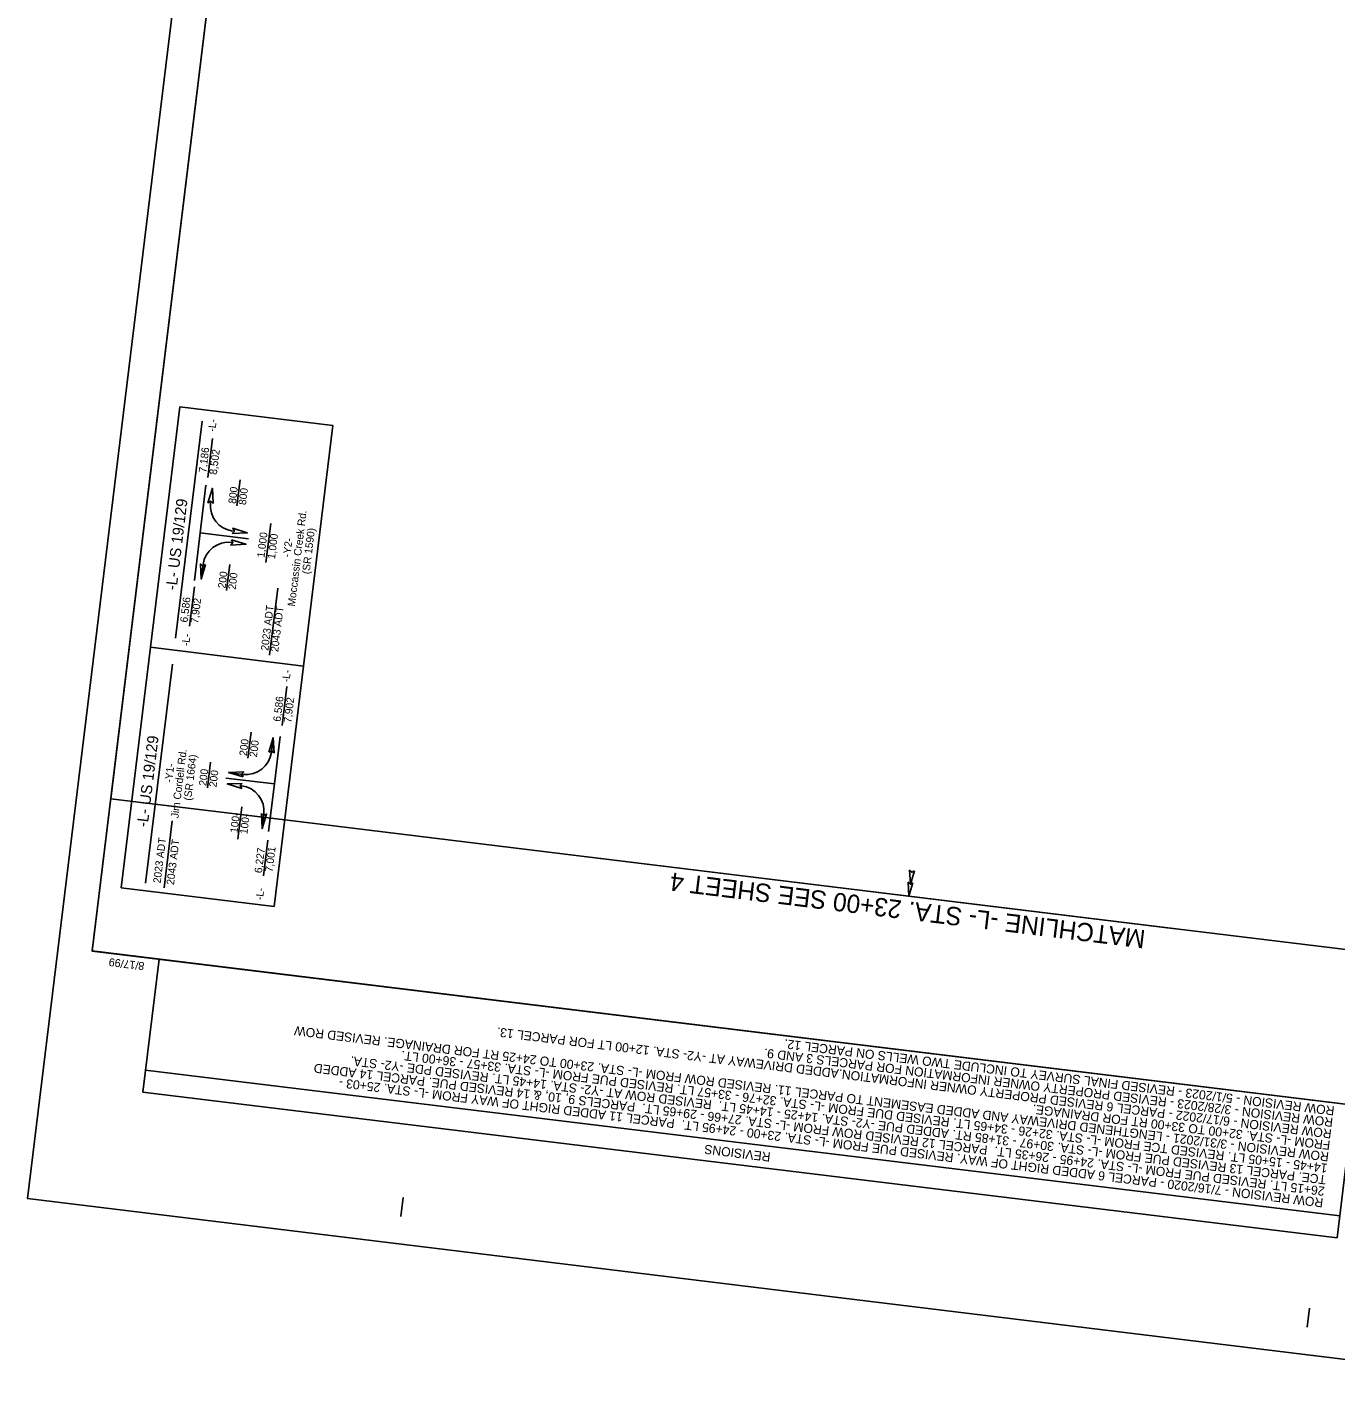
# Model space of a CAD drawing. Extents: x 480792 to 482083, y 490046 to 491850.
# Drawn here: x 480792 to 481651, y 490046 to 490948 of the extents above; entities that cross this region are included whole.
import ezdxf

# ---------------------------------------------------------------- set-up
doc = ezdxf.new("R2010")
doc.units = 0
for name, color, linetype in [('Matchline', 7, 'Continuous'), ('Matchline Text', 7, 'Continuous'), ('Prop DSN Text', 7, 'Continuous'), ('Prop Grid Mask', 7, 'Continuous'), ('Prop PHM Traffic Signal CELL', 7, 'Continuous'), ('Prop Terminator CELL', 7, 'Continuous'), ('Sheet Block Revision CELL', 7, 'Continuous'), ('Sheet Clip Boundary CELL', 7, 'Continuous'), ('Sheet Plan CELL', 7, 'Continuous'), ('Sheet Plot Border Outside CELL', 7, 'Continuous')]:
    doc.layers.add(name, color=color, linetype=linetype)

msp = doc.modelspace()

# ---------------------------------------------------------------- linework, layer by layer
at = {"layer": 'Matchline'}
msp.add_line((481546.32, 490356.15), (481123.7, 490407.77), dxfattribs=at)
at = {"layer": 'Prop DSN Text'}
for p, q in [((480937.18, 490612.39), (480905.3, 490616.28)), ((480922.18, 490455.2), (480954.06, 490451.31)), ((480923.98, 490458.77), (480933.43, 490457.61))]:
    msp.add_line(p, q, dxfattribs=at)
for points in [[(480913.77, 490635.61), (480913.36, 490645.56), (480910.4, 490636.02), (480912.33, 490637.05)], [(480926.35, 490615.87), (480936.3, 490616.28), (480926.76, 490619.24), (480927.79, 490617.31)], [(480925.83, 490611.61), (480935.39, 490608.82), (480925.42, 490608.24), (480926.88, 490609.87)], [(480908.87, 490595.48), (480906.08, 490585.92), (480905.5, 490595.89), (480907.12, 490594.43)], [(480950.5, 490472.11), (480953.29, 490481.66), (480953.86, 490471.69), (480952.24, 490473.15)], [(480933.53, 490455.97), (480923.98, 490458.77), (480933.95, 490459.34), (480932.49, 490457.72)], [(480933.01, 490451.72), (480923.07, 490451.31), (480932.6, 490448.35), (480931.58, 490450.27)], [(480945.59, 490431.97), (480946.01, 490422.03), (480948.96, 490431.57), (480947.04, 490430.54)]]:
    msp.add_lwpolyline(points, close=True, dxfattribs=at)
for centre, start, end in [((480928.86, 490634.08), 173.08207, 263.08206), ((480923.89, 490593.33), 82.99191, 172.99189), ((480935.48, 490474.25), 262.99191, 352.99189), ((480930.5, 490433.51), 353.08207, 83.08206)]:
    msp.add_arc(centre, 16.77, start, end, dxfattribs=at)
at = {"layer": 'Prop Grid Mask'}
for points in [[(480872.76, 490541.08), (480892.05, 490698.98), (480992.53, 490686.71), (480973.24, 490528.81)], [(480853.48, 490383.18), (480872.76, 490541.08), (480973.24, 490528.81), (480953.96, 490370.91)]]:
    msp.add_lwpolyline(points, close=True, dxfattribs=at)
at = {"layer": 'Prop PHM Traffic Signal CELL'}
for p, q in [((480889.11, 490547.02), (480906.54, 490689.7)), ((480913.43, 490678.26), (480910.3, 490652.62)), ((480909.12, 490647.49), (480905.3, 490616.28)), ((480931.55, 490651.06), (480929.48, 490634.03)), ((480951.67, 490622.5), (480948.54, 490596.86)), ((480901.49, 490585.08), (480905.3, 490616.28)), ((480906.08, 490585.92), (480907.24, 490595.38)), ((480924.76, 490595.46), (480922.68, 490578.44)), ((480901.52, 490580.72), (480898.39, 490555.07)), ((480956.35, 490580), (480950.98, 490536.01)), ((480869.46, 490386.15), (480887.04, 490530.06)), ((480962.37, 490515.31), (480959.24, 490489.67)), ((480938.74, 490485.39), (480936.66, 490468.37)), ((480953.29, 490481.66), (480952.13, 490472.21)), ((480957.87, 490482.51), (480954.06, 490451.31)), ((480912.17, 490465.73), (480910.09, 490448.7)), ((480950.25, 490420.1), (480954.06, 490451.31)), ((480932.75, 490436.32), (480930.16, 490415.1)), ((480886.98, 490427.09), (480881.6, 490383.1)), ((480946.01, 490422.03), (480947.15, 490431.49)), ((480946.99, 490391.07), (480949.84, 490414.41))]:
    msp.add_line(p, q, dxfattribs=at)
at = {"layer": 'Prop Terminator CELL'}
for points in [[(481374.66, 490394.22), (481372.03, 490385.47), (481371.54, 490394.65), (481372.99, 490393.31)], [(481373.71, 490386.38), (481371.08, 490377.63), (481370.58, 490386.81), (481372.03, 490385.47)]]:
    msp.add_lwpolyline(points, close=True, dxfattribs=at)
at = {"layer": 'Sheet Block Revision CELL'}
msp.add_line((481654.27, 490167.56), (480869.47, 490263.4), dxfattribs=at)
msp.add_lwpolyline([(481652.43, 490153.13), (480867.72, 490248.97), (480878.34, 490336.23), (481663.05, 490240.39)], close=True, dxfattribs=at)
at = {"layer": 'Sheet Clip Boundary CELL'}
msp.add_lwpolyline([(480960.89, 490427.66), (481123.7, 490407.77), (481546.78, 490356.1), (481674.49, 490340.53), (481662.51, 490242.06), (481694.92, 490236.5), (481876.58, 490214.31), (482038.38, 491533.84), (481958.33, 491543.66), (481978.88, 491711.23), (481782.84, 491735.27), (481563.21, 491713.66), (481210.33, 491642.39), (481164.2, 491610.96), (481026.3, 491629.16), (480991.92, 491631.99), (480846.54, 490441.62)], close=True, dxfattribs=at)
at = {"layer": 'Sheet Plan CELL'}
for p, q in [((480834.33, 490341.61), (480834.33, 490341.61)), ((481037.21, 490167.23), (481038.7, 490179.65)), ((481632.77, 490094.51), (481634.3, 490106.92))]:
    msp.add_line(p, q, dxfattribs=at)
for points in [[(481016.19, 491830.58), (480834.33, 490341.61), (481876.58, 490214.31), (482058.44, 491703.26)], [(481876.58, 490214.31), (480834.35, 490341.58), (480991.92, 491631.99), (481140.87, 491613.81), (481165.14, 491812.37), (482058.44, 491703.26)]]:
    msp.add_lwpolyline(points, close=True, dxfattribs=at)
at = {"layer": 'Sheet Plot Border Outside CELL'}
msp.add_lwpolyline([(481878.74, 490046.32), (482082.84, 491717.41), (480995.92, 491850.16), (480791.82, 490179.08)], close=True, dxfattribs=at)

# ---------------------------------------------------------------- texts
at = {"layer": 'Matchline Text'}
msp.add_text('MATCHLINE -L- STA. 23+00 SEE SHEET 4', height=12, rotation=173.03651, dxfattribs=at).set_placement((481526.97, 490355.15))
at = {"layer": 'Prop PHM Traffic Signal CELL'}
for s, height, rotation, p in [('-L-', 5, 83.03694, (480915.27, 490682.57)), ('7,186', 5, 83.03694, (480909.32, 490655.57)), ('8,502', 5, 83.03694, (480916.22, 490654.27)), ('800', 5, 83.03694, (480928.73, 490635.19)), ('800', 5, 83.03694, (480935.41, 490634.37)), ('-L- US 19/129', 7.25, 83.03651, (480889.76, 490578.32)), ('Moccassin Creek Rd. ', 5, 83.037, (480967.6, 490567.73)), ('1,000', 5, 83.03694, (480947.56, 490599.79)), ('(SR 1590)', 5, 83.037, (480977.18, 490588.94)), ('1,000', 5, 83.03694, (480954.49, 490598.84)), ('-Y2-', 5, 83.037, (480964.57, 490600.09)), ('200', 5, 83.03694, (480921.94, 490579.59)), ('200', 5, 83.03694, (480928.62, 490578.77)), ('6,586', 5, 83.03694, (480897, 490557.2)), ('7,902', 5, 83.03694, (480903.97, 490556.51)), ('2023 ADT', 5, 83.03694, (480950.09, 490538.62)), ('2043 ADT', 5, 83.03694, (480956.57, 490537.83)), ('-L-', 5, 83.03694, (480898.06, 490541.66)), ('-L-', 5, 83.03694, (480964, 490517.93)), ('6,586', 5, 83.03694, (480958.19, 490492.02)), ('7,902', 5, 83.03694, (480965.16, 490491.32)), ('-L- US 19/129', 7.25, 83.03651, (480870.76, 490422.73)), ('Jim Cordell Rd. ', 5, 83.03694, (480891.04, 490428.66)), ('200', 5, 83.03694, (480935.92, 490469.52)), ('200', 5, 83.03694, (480942.59, 490468.7)), ('-Y1-', 5, 83.03694, (480886.89, 490451.89)), ('(SR 1664)', 5, 83.03694, (480899.42, 490440.15)), ('200', 5, 83.03694, (480909.35, 490449.85)), ('200', 5, 83.03694, (480916.02, 490449.04)), ('100-', 5, 83.03694, (480929.85, 490418.97)), ('100-', 5, 83.03694, (480936.33, 490418.18)), ('2023 ADT', 5, 83.03694, (480879.32, 490385.88)), ('2043 ADT', 5, 83.03694, (480888.09, 490384.81)), ('6,227', 5, 83.03703, (480945.88, 490392.53)), ('7,001', 5, 83.03703, (480952.94, 490393.25)), ('-L-', 5, 83.03694, (480946.52, 490374.81))]:
    msp.add_text(s, height=height, rotation=rotation, dxfattribs=at).set_placement(p)
at = {"layer": 'Sheet Block Revision CELL'}
for s, p in [('ROW REVISION - 3/31/2021 - LENGTHENED DRIVEWAY AND ADDED EASEMENT TO PARCEL 11. REVISED ROW FROM -L- STA. 23+00 TO 24+25 RT FOR DRAINAGE. REVISED ROW ', (481647.33, 490209.29)), ('ROW REVISION - 6/17/2022 - PARCEL 6 REVISED PROPERTY OWNER INFORMATION.ADDED DRIVEWAY AT -Y2- STA. 12+00 LT FOR PARCEL 13. ', (481649.17, 490224.39)), ('ROW REVISION - 5/1/2023 - REVISED FINAL SURVEY TO INCLUDE TWO WELLS ON PARCEL 12.', (481651.02, 490239.49)), ('14+45 - 15+05 LT. REVISED TCE FROM -L- STA. 32+26 - 34+65 LT. REVISED DUE FROM -L- STA. 32+76 - 33+57 LT. REVISED PUE FROM -L- STA. 33+57 - 36+00 LT.', (481646.41, 490201.74)), ('ROW REVISION - 3/28/2023 - REVISED PROPERTY OWNER INFORMATION FOR PARCELS 3 AND 9. ', (481650.09, 490231.94)), ('26+15 LT. REVISED PUE FROM -L- STA. 24+95 - 26+35 LT.  PARCEL 12 REVISED ROW FROM -L- STA. 27+66 - 29+65 LT.  PARCELS 9, 10, & 14 REVISED PUE. PARCEL 14 ADDED ', (481644.56, 490186.64)), ('TCE. PARCEL 13 REVISED PUE FROM -L- STA. 30+97 - 31+85 RT. ADDED PUE -Y2- STA. 14+25 - 14+45 LT.  REVISED ROW AT -Y2- STA. 14+45 LT. REVISED PDE -Y2- STA. ', (481645.48, 490194.19)), ('ROW REVISION - 7/16/2020 - PARCEL 6 ADDED RIGHT OF WAY. REVISED PUE FROM -L- STA. 23+00 - 24+95 LT.  PARCEL 11 ADDED RIGHT OF WAY FROM -L- STA. 25+03 - ', (481643.64, 490179.09)), ('FROM -L- STA. 32+00 TO 33+00 RT FOR DRAINAGE.', (481648.25, 490216.84)), ('REVISIONS', (481280.41, 490209.14))]:
    msp.add_text(s, height=6, rotation=173.03651, dxfattribs=at).set_placement(p)
at = {"layer": 'Sheet Plan CELL'}
msp.add_text('8/17/99', height=5.25, rotation=173.03652, dxfattribs=at).set_placement((480868.9, 490334.14))

doc.saveas('drawing.dxf')
